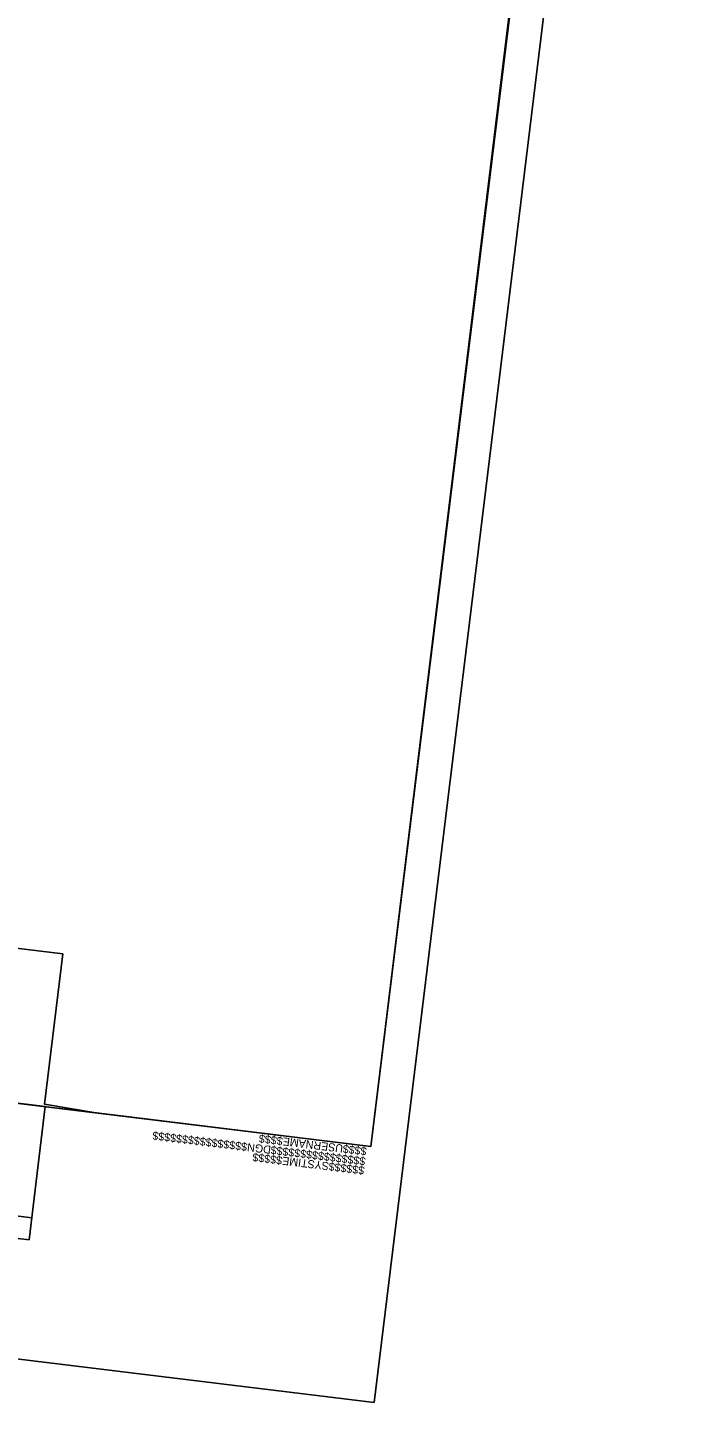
# Model space of a CAD drawing. Extents: x 480792 to 482083, y 490046 to 491850.
# Drawn here: x 481651 to 482083, y 490046 to 490948 of the extents above; entities that cross this region are included whole.
import ezdxf

# ---------------------------------------------------------------- set-up
doc = ezdxf.new("R2010")
doc.units = 0
for name, color, linetype in [('Sheet Block Revision CELL', 7, 'Continuous'), ('Sheet Clip Boundary CELL', 7, 'Continuous'), ('Sheet Plan CELL', 7, 'Continuous'), ('Sheet Plot Border Outside CELL', 7, 'Continuous')]:
    doc.layers.add(name, color=color, linetype=linetype)

msp = doc.modelspace()

# ---------------------------------------------------------------- linework, layer by layer
at = {"layer": 'Sheet Block Revision CELL'}
msp.add_line((481654.27, 490167.56), (480869.47, 490263.4), dxfattribs=at)
msp.add_lwpolyline([(481652.43, 490153.13), (480867.72, 490248.97), (480878.34, 490336.23), (481663.05, 490240.39)], close=True, dxfattribs=at)
at = {"layer": 'Sheet Clip Boundary CELL'}
msp.add_lwpolyline([(480960.89, 490427.66), (481123.7, 490407.77), (481546.78, 490356.1), (481674.49, 490340.53), (481662.51, 490242.06), (481694.92, 490236.5), (481876.58, 490214.31), (482038.38, 491533.84), (481958.33, 491543.66), (481978.88, 491711.23), (481782.84, 491735.27), (481563.21, 491713.66), (481210.33, 491642.39), (481164.2, 491610.96), (481026.3, 491629.16), (480991.92, 491631.99), (480846.54, 490441.62)], close=True, dxfattribs=at)
at = {"layer": 'Sheet Plan CELL'}
msp.add_line((481876.58, 490214.31), (481876.58, 490214.31), dxfattribs=at)
for points in [[(481016.19, 491830.58), (480834.33, 490341.61), (481876.58, 490214.31), (482058.44, 491703.26)], [(481876.58, 490214.31), (480834.35, 490341.58), (480991.92, 491631.99), (481140.87, 491613.81), (481165.14, 491812.37), (482058.44, 491703.26)]]:
    msp.add_lwpolyline(points, close=True, dxfattribs=at)
at = {"layer": 'Sheet Plot Border Outside CELL'}
msp.add_lwpolyline([(481878.74, 490046.32), (482082.84, 491717.41), (480995.92, 491850.16), (480791.82, 490179.08)], close=True, dxfattribs=at)

# ---------------------------------------------------------------- texts
at = {"layer": 'Sheet Plan CELL'}
for s, p in [('$$$$$$$$$$$$$$$$DGN$$$$$$$$$$$$$$$$', (481873.31, 490207.02)), ('$$$$USERNAME$$$$', (481874.09, 490213.52)), ('$$$$$$SYSTIME$$$$$', (481872.6, 490200.98))]:
    msp.add_text(s, height=5.25, rotation=173.03652, dxfattribs=at).set_placement(p)

doc.saveas('drawing.dxf')
